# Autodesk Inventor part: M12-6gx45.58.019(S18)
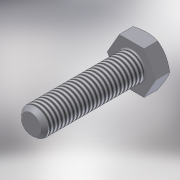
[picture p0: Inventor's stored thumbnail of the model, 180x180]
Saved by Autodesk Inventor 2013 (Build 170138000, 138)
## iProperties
Shininess: 25.0
Length Units: 11269
Angle Units: 11279
Time Units: 11290
Mass Units: 11283
Length Display Precision: 3
Angle Display Precision: 2
Created: 2001-10
Material: Steel, Mild
Description: Болт М12-6gх45.58.019(S18) ГОСТ 7798-70
Document SubType Name: Modeling
Designer: TEvgeniy
Mass: 57.7422 g
Surface Area: 27.2183 cm^2
Volume: 7.34634 cm^3
Density: 7.86 g/cm^3
Density: 0.0
Volumn: 0.0
Area: 0.0
PropertySet Name: Model Information
Control State: 0
Master: False
Checked Out: True
Checked Out Date: 2008-10-15
Last Check In Date: 2008-10-15
Author: TEvgeniy
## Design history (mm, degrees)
sketch "Sketch1"
  geometry: L1 (485.544, 469.325)-(474.575, 469.325); L2 (491.029, 459.825)-(485.544, 469.325); L3 (485.544, 450.325)-(491.029, 459.825); L4 (474.575, 450.325)-(485.544, 450.325); L5 (469.09, 459.825)-(474.575, 450.325); L6 (474.575, 469.325)-(469.09, 459.825); C1 r 9.5 at (480.059, 459.825)
  constraints: 12 end point, 6 tangent, 3 parallel, 1 centre point, 1 horizontal, 1 other
  dimensions: "d1" = 120 deg angle of L1 L2; "d3" = 120 deg angle of L5 L6; "d5" = 19 diameter of C1
extrude "ExtrusionBlind1" new body sketch "Sketch1" distance "d6" = 7.5; taper "d7" = 0 deg
sketch "Sketch2"
  geometry: C1 r 8.4 at (480.059, -459.825)
  constraints: 1 centre point
  dimensions: "d12" = 16.8 diameter of C1
extrude "ExtrusionThru1" sketch "Sketch2" stored distance "d13" = 0.13; taper "d14" = 60 deg
sketch "Sketch3"
  geometry: L1 (469.09, 459.825)-(469.59, 460.691); L2 (474.575, 469.325)-(475.575, 469.325); L3 (485.544, 469.325)-(486.044, 468.459); C1 r 6 at (480.059, 459.825); C2 r 9.5 at (480.059, 459.825)
  constraints: 6 end point, 3 tangent, 2 centre point, 1 coincident
  dimensions: "d16" = 12 diameter of C1
extrude "ExtrusionBlind2" join sketch "Sketch3" distance "d17" = 45; taper "d18" = 0 deg
fillet "Fillet1" dims "d19" = 0.5
chamfer "Chamfer1" distance "d20" = 1.6; stored, may be unused: second distance "d21" = 1.6, angle "d26" = 45 deg
thread "Thread1" dims "d22" = 10, "d23" = 0
body "Solid1"
other parameters: "d0" = 120 deg (derived), "d2" = 120 deg (derived), "d4" = 19 (derived), "d8" = 0, "d9" = 0, "d10" = 0, "d11" = 16.8 (derived), "d15" = 12 (derived)
